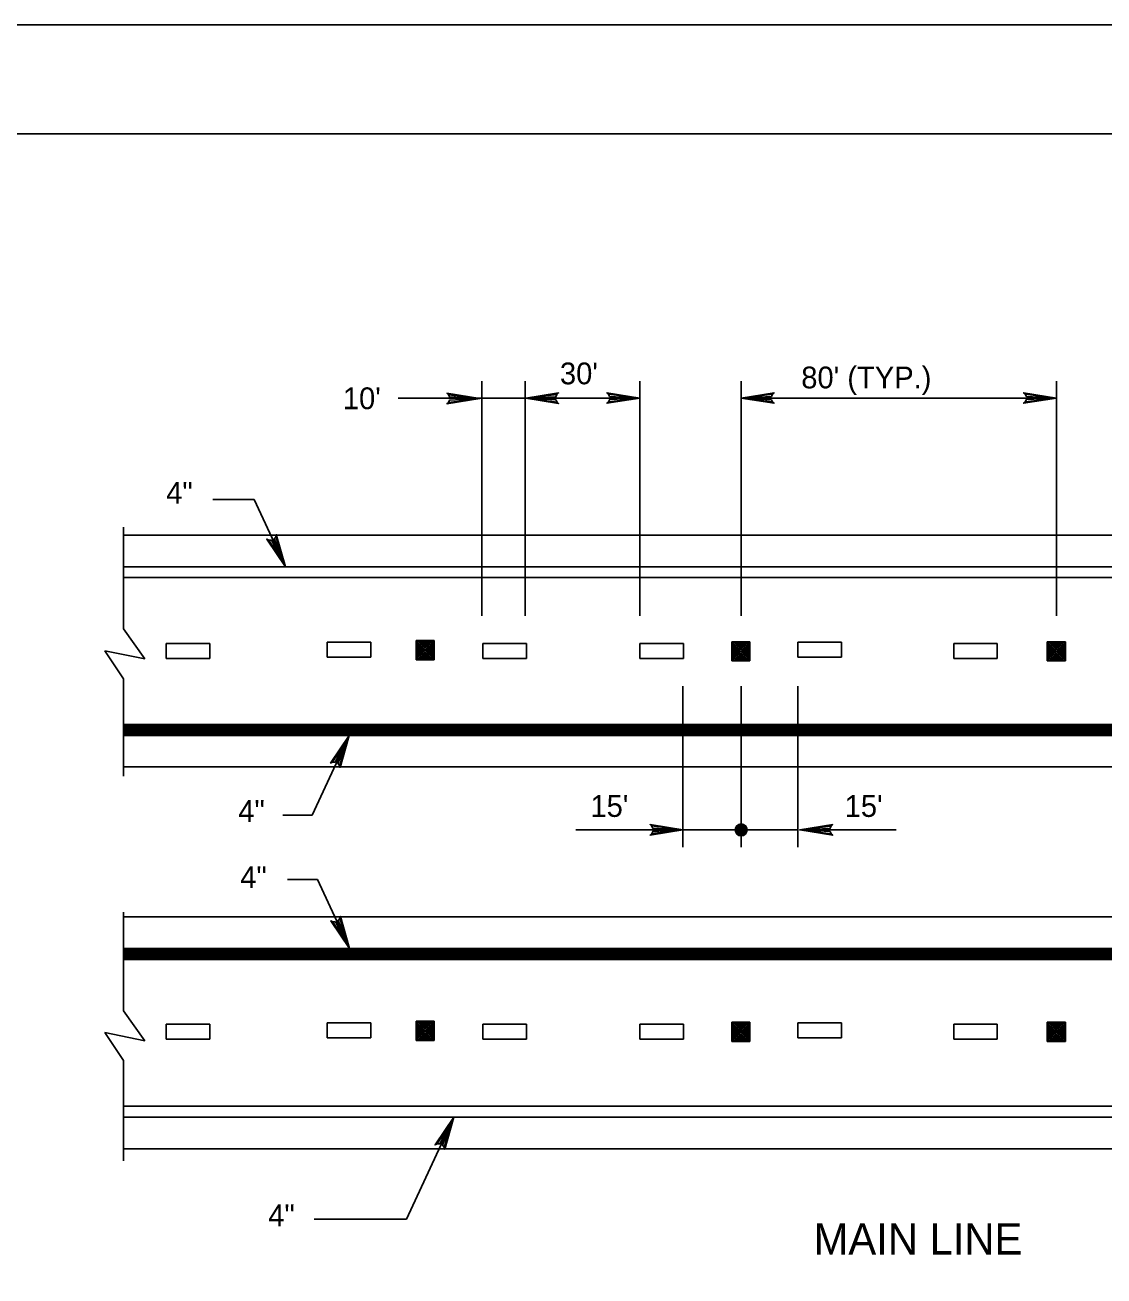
# Model space of a CAD drawing. Extents: x 639362 to 641108, y 298458 to 299646.
# Drawn here: x 639830.9 to 639979.6, y 299473.3 to 299645.6 of the extents above; entities that cross this region are included whole.
import ezdxf

# ---------------------------------------------------------------- set-up
doc = ezdxf.new("R2010")
doc.units = 0
for name, color, linetype in [('1', 7, 'Continuous'), ('2', 7, 'Continuous'), ('PLT-BNDY', 7, 'Continuous')]:
    doc.layers.add(name, color=color, linetype=linetype)

msp = doc.modelspace()

# ---------------------------------------------------------------- linework, layer by layer
at = {"layer": '1'}
msp.add_line((639402.31, 299630.63), (640188.31, 299630.63), dxfattribs=at)
at = {"layer": '2'}
for p, q in [((639893.88, 299564.2), (639893.88, 299596.53)), ((639899.82, 299564.2), (639899.82, 299596.53)), ((639915.64, 299564.2), (639915.64, 299596.53)), ((639929.6, 299564.2), (639929.6, 299596.53)), ((639973.04, 299564.2), (639973.04, 299596.53)), ((639882.34, 299594.23), (639899.82, 299594.23)), ((639899.82, 299594.23), (639915.64, 299594.23)), ((639973.04, 299594.23), (639929.6, 299594.23)), ((639856.81, 299580.26), (639862.49, 299580.26)), ((639862.49, 299580.26), (639866.8, 299570.98)), ((639844.48, 299576.44), (639844.48, 299562.41)), ((639844.48, 299575.33), (640078.99, 299575.33)), ((639844.48, 299570.98), (640078.99, 299570.98)), ((639844.48, 299569.48), (640078.99, 299569.48)), ((639847.43, 299558.27), (639844.48, 299562.41)), ((639850.37, 299558.33), (639850.37, 299560.39)), ((639850.37, 299560.39), (639856.39, 299560.39)), ((639856.39, 299560.39), (639856.39, 299558.33)), ((639872.56, 299558.51), (639872.56, 299560.58)), ((639872.56, 299560.58), (639878.58, 299560.58)), ((639878.58, 299560.58), (639878.58, 299558.51)), ((639887.32, 299560.81), (639884.82, 299560.81)), ((639884.82, 299560.81), (639884.82, 299558.16)), ((639887.13, 299560.68), (639885.01, 299560.68)), ((639885.01, 299560.68), (639885.01, 299558.29)), ((639886.96, 299560.51), (639885.18, 299560.51)), ((639885.18, 299560.51), (639885.18, 299558.47)), ((639886.78, 299560.33), (639885.36, 299560.33)), ((639885.36, 299560.33), (639885.36, 299558.64)), ((639886.6, 299560.15), (639885.54, 299560.15)), ((639885.54, 299560.15), (639885.54, 299558.82)), ((639886.6, 299558.82), (639886.6, 299560.15)), ((639886.78, 299558.64), (639886.78, 299560.33)), ((639886.96, 299558.47), (639886.96, 299560.51)), ((639887.13, 299558.29), (639887.13, 299560.68)), ((639887.32, 299558.16), (639887.32, 299560.81)), ((639894.01, 299558.33), (639894.01, 299560.39)), ((639894.01, 299560.39), (639900.02, 299560.39)), ((639900.02, 299560.39), (639900.02, 299558.33)), ((639915.64, 299558.33), (639915.64, 299560.39)), ((639915.64, 299560.39), (639921.65, 299560.39)), ((639921.65, 299560.39), (639921.65, 299558.33)), ((639928.31, 299560.65), (639930.81, 299560.65)), ((639928.31, 299558), (639928.31, 299560.65)), ((639928.5, 299560.52), (639930.63, 299560.52)), ((639928.5, 299558.12), (639928.5, 299560.52)), ((639928.68, 299560.34), (639930.45, 299560.34)), ((639928.68, 299558.3), (639928.68, 299560.34)), ((639928.85, 299560.16), (639930.27, 299560.16)), ((639928.85, 299558.48), (639928.85, 299560.16)), ((639930.27, 299560.16), (639930.27, 299558.48)), ((639930.45, 299560.34), (639930.45, 299558.3)), ((639930.63, 299560.52), (639930.63, 299558.12)), ((639930.81, 299560.65), (639930.81, 299558)), ((639937.42, 299558.51), (639937.42, 299560.58)), ((639937.42, 299560.58), (639943.44, 299560.58)), ((639943.44, 299560.58), (639943.44, 299558.51)), ((639958.88, 299558.33), (639958.88, 299560.39)), ((639958.88, 299560.39), (639964.89, 299560.39)), ((639964.89, 299560.39), (639964.89, 299558.33)), ((639974.28, 299560.65), (639971.78, 299560.65)), ((639971.78, 299560.65), (639971.78, 299558)), ((639974.09, 299560.52), (639971.96, 299560.52)), ((639971.96, 299560.52), (639971.96, 299558.12)), ((639973.92, 299560.34), (639972.14, 299560.34)), ((639972.14, 299560.34), (639972.14, 299558.3)), ((639973.74, 299560.16), (639972.32, 299560.16)), ((639972.32, 299560.16), (639972.32, 299558.48)), ((639973.74, 299558.48), (639973.74, 299560.16)), ((639973.92, 299558.3), (639973.92, 299560.34)), ((639974.09, 299558.12), (639974.09, 299560.52)), ((639974.28, 299558), (639974.28, 299560.65)), ((639844.48, 299555.54), (639841.91, 299559.41)), ((639841.91, 299559.41), (639847.43, 299558.27)), ((639878.58, 299558.51), (639872.56, 299558.51)), ((639885.18, 299558.47), (639886.96, 299558.47)), ((639885.36, 299558.64), (639886.78, 299558.64)), ((639885.54, 299558.82), (639886.6, 299558.82)), ((639885.71, 299559.97), (639885.71, 299559)), ((639886.43, 299559.97), (639885.71, 299559.97)), ((639885.71, 299559), (639886.43, 299559)), ((639886.25, 299559.79), (639885.89, 299559.79)), ((639885.89, 299559.79), (639885.89, 299559.17)), ((639885.89, 299559.17), (639886.25, 299559.17)), ((639886.07, 299559.62), (639886.07, 299559.35)), ((639886.25, 299559.17), (639886.25, 299559.79)), ((639886.43, 299559), (639886.43, 299559.97)), ((639930.27, 299558.48), (639928.85, 299558.48)), ((639929.03, 299559.99), (639930.1, 299559.99)), ((639929.03, 299558.66), (639929.03, 299559.99)), ((639930.1, 299558.66), (639929.03, 299558.66)), ((639929.21, 299558.83), (639929.21, 299559.81)), ((639929.21, 299559.81), (639929.92, 299559.81)), ((639929.92, 299558.83), (639929.21, 299558.83)), ((639929.39, 299559.63), (639929.74, 299559.63)), ((639929.39, 299559.01), (639929.39, 299559.63)), ((639929.74, 299559.01), (639929.39, 299559.01)), ((639929.56, 299559.45), (639929.56, 299559.19)), ((639929.74, 299559.63), (639929.74, 299559.01)), ((639929.92, 299559.81), (639929.92, 299558.83)), ((639930.1, 299559.99), (639930.1, 299558.66)), ((639943.44, 299558.51), (639937.42, 299558.51)), ((639972.32, 299558.48), (639973.74, 299558.48)), ((639973.56, 299559.99), (639972.5, 299559.99)), ((639972.5, 299559.99), (639972.5, 299558.66)), ((639972.5, 299558.66), (639973.56, 299558.66)), ((639972.67, 299559.81), (639972.67, 299558.83)), ((639973.38, 299559.81), (639972.67, 299559.81)), ((639972.67, 299558.83), (639973.38, 299558.83)), ((639973.2, 299559.63), (639972.85, 299559.63)), ((639972.85, 299559.63), (639972.85, 299559.01)), ((639972.85, 299559.01), (639973.2, 299559.01)), ((639973.03, 299559.45), (639973.03, 299559.19)), ((639973.2, 299559.01), (639973.2, 299559.63)), ((639973.38, 299558.83), (639973.38, 299559.81)), ((639973.56, 299558.66), (639973.56, 299559.99)), ((639856.39, 299558.33), (639850.37, 299558.33)), ((639884.82, 299558.16), (639887.32, 299558.16)), ((639885.01, 299558.29), (639887.13, 299558.29)), ((639900.02, 299558.33), (639894.01, 299558.33)), ((639921.65, 299558.33), (639915.64, 299558.33)), ((639930.81, 299558), (639928.31, 299558)), ((639930.63, 299558.12), (639928.5, 299558.12)), ((639930.45, 299558.3), (639928.68, 299558.3)), ((639964.89, 299558.33), (639958.88, 299558.33)), ((639971.78, 299558), (639974.28, 299558)), ((639971.96, 299558.12), (639974.09, 299558.12)), ((639972.14, 299558.3), (639973.92, 299558.3)), ((639844.48, 299555.54), (639844.48, 299542.1)), ((639921.57, 299554.52), (639921.57, 299532.35)), ((639929.6, 299554.52), (639929.6, 299532.35)), ((639937.4, 299554.52), (639937.4, 299532.35)), ((639844.48, 299549.24), (640078.99, 299549.24)), ((639844.48, 299549.09), (640078.99, 299549.09)), ((639844.48, 299548.94), (640078.99, 299548.94)), ((639844.48, 299548.79), (640078.99, 299548.79)), ((639844.48, 299548.64), (640078.99, 299548.64)), ((639844.48, 299548.49), (640078.99, 299548.49)), ((639844.48, 299548.34), (640078.99, 299548.34)), ((639844.48, 299548.19), (640078.99, 299548.19)), ((639844.48, 299548.04), (640078.99, 299548.04)), ((639844.48, 299547.89), (640078.99, 299547.89)), ((639844.48, 299547.74), (640078.99, 299547.74)), ((639870.5, 299536.76), (639875.59, 299547.74)), ((639844.48, 299543.39), (640078.99, 299543.39)), ((639866.45, 299536.76), (639870.5, 299536.76)), ((639921.57, 299534.72), (639906.84, 299534.72)), ((639921.57, 299534.72), (639937.4, 299534.72)), ((639937.63, 299534.72), (639950.97, 299534.72)), ((639867.08, 299527.87), (639871.22, 299527.87)), ((639871.22, 299527.87), (639875.63, 299518.37)), ((639844.48, 299523.39), (639844.48, 299509.8)), ((639844.48, 299522.72), (640078.99, 299522.72)), ((639844.48, 299518.37), (640078.99, 299518.37)), ((639844.48, 299518.22), (640078.99, 299518.22)), ((639844.48, 299518.07), (640078.99, 299518.07)), ((639844.48, 299517.92), (640078.99, 299517.92)), ((639844.48, 299517.77), (640078.99, 299517.77)), ((639844.48, 299517.62), (640078.99, 299517.62)), ((639844.48, 299517.47), (640078.99, 299517.47)), ((639844.48, 299517.32), (640078.99, 299517.32)), ((639844.48, 299517.17), (640078.99, 299517.17)), ((639844.48, 299517.02), (640078.99, 299517.02)), ((639844.48, 299516.87), (640078.99, 299516.87)), ((639847.43, 299505.67), (639844.48, 299509.8)), ((639844.48, 299502.93), (639841.91, 299506.8)), ((639841.91, 299506.8), (639847.43, 299505.67)), ((639850.37, 299505.88), (639850.37, 299507.94)), ((639850.37, 299507.94), (639856.39, 299507.94)), ((639856.39, 299507.94), (639856.39, 299505.88)), ((639872.56, 299506.07), (639872.56, 299508.13)), ((639872.56, 299508.13), (639878.58, 299508.13)), ((639878.58, 299508.13), (639878.58, 299506.07)), ((639887.32, 299508.37), (639884.82, 299508.37)), ((639884.82, 299508.37), (639884.82, 299505.71)), ((639887.13, 299508.24), (639885.01, 299508.24)), ((639885.01, 299508.24), (639885.01, 299505.84)), ((639886.96, 299508.06), (639885.18, 299508.06)), ((639885.18, 299508.06), (639885.18, 299506.02)), ((639886.78, 299507.88), (639885.36, 299507.88)), ((639885.36, 299507.88), (639885.36, 299506.2)), ((639886.6, 299507.7), (639885.54, 299507.7)), ((639885.54, 299507.7), (639885.54, 299506.37)), ((639885.71, 299507.53), (639885.71, 299506.55)), ((639886.43, 299507.53), (639885.71, 299507.53)), ((639886.25, 299507.35), (639885.89, 299507.35)), ((639885.89, 299507.35), (639885.89, 299506.73)), ((639885.89, 299506.73), (639886.25, 299506.73)), ((639886.07, 299507.17), (639886.07, 299506.91)), ((639886.25, 299506.73), (639886.25, 299507.35)), ((639886.43, 299506.55), (639886.43, 299507.53)), ((639886.6, 299506.37), (639886.6, 299507.7)), ((639886.78, 299506.2), (639886.78, 299507.88)), ((639886.96, 299506.02), (639886.96, 299508.06)), ((639887.13, 299505.84), (639887.13, 299508.24)), ((639887.32, 299505.71), (639887.32, 299508.37)), ((639894.01, 299505.88), (639894.01, 299507.94)), ((639894.01, 299507.94), (639900.02, 299507.94)), ((639900.02, 299507.94), (639900.02, 299505.88)), ((639915.64, 299505.88), (639915.64, 299507.94)), ((639915.64, 299507.94), (639921.65, 299507.94)), ((639921.65, 299507.94), (639921.65, 299505.88)), ((639928.31, 299508.21), (639930.81, 299508.21)), ((639928.31, 299505.55), (639928.31, 299508.21)), ((639928.5, 299508.07), (639930.63, 299508.07)), ((639928.5, 299505.68), (639928.5, 299508.07)), ((639928.68, 299507.9), (639930.45, 299507.9)), ((639928.68, 299505.86), (639928.68, 299507.9)), ((639928.85, 299507.72), (639930.27, 299507.72)), ((639928.85, 299506.03), (639928.85, 299507.72)), ((639929.03, 299507.54), (639930.1, 299507.54)), ((639929.03, 299506.21), (639929.03, 299507.54)), ((639929.21, 299506.39), (639929.21, 299507.36)), ((639929.21, 299507.36), (639929.92, 299507.36)), ((639929.39, 299507.19), (639929.74, 299507.19)), ((639929.39, 299506.57), (639929.39, 299507.19)), ((639929.56, 299507.01), (639929.56, 299506.74)), ((639929.74, 299507.19), (639929.74, 299506.57)), ((639929.92, 299507.36), (639929.92, 299506.39)), ((639930.1, 299507.54), (639930.1, 299506.21)), ((639930.27, 299507.72), (639930.27, 299506.03)), ((639930.45, 299507.9), (639930.45, 299505.86)), ((639930.63, 299508.07), (639930.63, 299505.68)), ((639930.81, 299508.21), (639930.81, 299505.55)), ((639937.42, 299506.07), (639937.42, 299508.13)), ((639937.42, 299508.13), (639943.44, 299508.13)), ((639943.44, 299508.13), (639943.44, 299506.07)), ((639958.88, 299505.88), (639958.88, 299507.94)), ((639958.88, 299507.94), (639964.89, 299507.94)), ((639964.89, 299507.94), (639964.89, 299505.88)), ((639974.28, 299508.21), (639971.78, 299508.21)), ((639971.78, 299508.21), (639971.78, 299505.55)), ((639974.09, 299508.07), (639971.96, 299508.07)), ((639971.96, 299508.07), (639971.96, 299505.68)), ((639973.92, 299507.9), (639972.14, 299507.9)), ((639972.14, 299507.9), (639972.14, 299505.86)), ((639973.74, 299507.72), (639972.32, 299507.72)), ((639972.32, 299507.72), (639972.32, 299506.03)), ((639973.56, 299507.54), (639972.5, 299507.54)), ((639972.5, 299507.54), (639972.5, 299506.21)), ((639972.67, 299507.36), (639972.67, 299506.39)), ((639973.38, 299507.36), (639972.67, 299507.36)), ((639973.2, 299507.19), (639972.85, 299507.19)), ((639972.85, 299507.19), (639972.85, 299506.57)), ((639973.03, 299507.01), (639973.03, 299506.74)), ((639973.2, 299506.57), (639973.2, 299507.19)), ((639973.38, 299506.39), (639973.38, 299507.36)), ((639973.56, 299506.21), (639973.56, 299507.54)), ((639973.74, 299506.03), (639973.74, 299507.72)), ((639973.92, 299505.86), (639973.92, 299507.9)), ((639974.09, 299505.68), (639974.09, 299508.07)), ((639974.28, 299505.55), (639974.28, 299508.21)), ((639856.39, 299505.88), (639850.37, 299505.88)), ((639878.58, 299506.07), (639872.56, 299506.07)), ((639884.82, 299505.71), (639887.32, 299505.71)), ((639885.01, 299505.84), (639887.13, 299505.84)), ((639885.18, 299506.02), (639886.96, 299506.02)), ((639885.36, 299506.2), (639886.78, 299506.2)), ((639885.54, 299506.37), (639886.6, 299506.37)), ((639885.71, 299506.55), (639886.43, 299506.55)), ((639900.02, 299505.88), (639894.01, 299505.88)), ((639921.65, 299505.88), (639915.64, 299505.88)), ((639930.81, 299505.55), (639928.31, 299505.55)), ((639930.63, 299505.68), (639928.5, 299505.68)), ((639930.45, 299505.86), (639928.68, 299505.86)), ((639930.27, 299506.03), (639928.85, 299506.03)), ((639930.1, 299506.21), (639929.03, 299506.21)), ((639929.92, 299506.39), (639929.21, 299506.39)), ((639929.74, 299506.57), (639929.39, 299506.57)), ((639943.44, 299506.07), (639937.42, 299506.07)), ((639964.89, 299505.88), (639958.88, 299505.88)), ((639971.78, 299505.55), (639974.28, 299505.55)), ((639971.96, 299505.68), (639974.09, 299505.68)), ((639972.14, 299505.86), (639973.92, 299505.86)), ((639972.32, 299506.03), (639973.74, 299506.03)), ((639972.5, 299506.21), (639973.56, 299506.21)), ((639972.67, 299506.39), (639973.38, 299506.39)), ((639972.85, 299506.57), (639973.2, 299506.57)), ((639844.48, 299502.93), (639844.48, 299489.11)), ((639844.48, 299496.64), (640078.99, 299496.64)), ((639844.48, 299495.14), (640078.99, 299495.14)), ((639883.47, 299481.07), (639890, 299495.14)), ((639844.48, 299490.79), (640078.99, 299490.79)), ((639870.78, 299481.07), (639883.47, 299481.07))]:
    msp.add_line(p, q, dxfattribs=at)
for points in [[(639889.26, 299594.69), (639889.43, 299594.38), (639893.58, 299594.15), (639889.26, 299594.69), (639889.05, 299594.88), (639893.58, 299594.15), (639889.43, 299593.94), (639889.28, 299593.63), (639893.58, 299594.15), (639889.05, 299593.43), (639889.28, 299593.63)], [(639904.23, 299593.67), (639904.07, 299593.97), (639899.91, 299594.2), (639904.23, 299593.67), (639904.45, 299593.47), (639899.91, 299594.2), (639904.07, 299594.41), (639904.22, 299594.72), (639899.91, 299594.2), (639904.45, 299594.93), (639904.22, 299594.72)], [(639911.32, 299594.77), (639911.48, 299594.46), (639915.64, 299594.23), (639911.32, 299594.77), (639911.11, 299594.96), (639915.64, 299594.23), (639911.49, 299594.03), (639911.34, 299593.72), (639915.64, 299594.23), (639911.11, 299593.51), (639911.34, 299593.72)], [(639933.92, 299593.69), (639933.76, 299594), (639929.6, 299594.23), (639933.92, 299593.69), (639934.14, 299593.5), (639929.6, 299594.23), (639933.76, 299594.44), (639933.91, 299594.75), (639929.6, 299594.23), (639934.14, 299594.95), (639933.91, 299594.75)], [(639968.73, 299594.77), (639968.89, 299594.46), (639973.04, 299594.23), (639968.73, 299594.77), (639968.5, 299594.96), (639973.04, 299594.23), (639968.89, 299594.03), (639968.74, 299593.72), (639973.04, 299594.23), (639968.5, 299593.51), (639968.74, 299593.72)], [(639865.47, 299575.12), (639865.26, 299574.85), (639866.8, 299570.98), (639865.47, 299575.12), (639865.55, 299575.4), (639866.8, 299570.98), (639864.87, 299574.66), (639864.52, 299574.66), (639866.8, 299570.98), (639864.23, 299574.79), (639864.52, 299574.66)], [(639874.26, 299543.6), (639874.05, 299543.87), (639875.59, 299547.74), (639874.26, 299543.6), (639874.34, 299543.32), (639875.59, 299547.74), (639873.66, 299544.06), (639873.31, 299544.05), (639875.59, 299547.74), (639873.03, 299543.93), (639873.31, 299544.05)], [(639917.26, 299535.26), (639917.42, 299534.95), (639921.57, 299534.72), (639917.26, 299535.26), (639917.04, 299535.45), (639921.57, 299534.72), (639917.42, 299534.52), (639917.27, 299534.2), (639921.57, 299534.72), (639917.04, 299534), (639917.27, 299534.2)], [(639942, 299534.18), (639941.84, 299534.49), (639937.68, 299534.72), (639942, 299534.18), (639942.22, 299533.99), (639937.68, 299534.72), (639941.83, 299534.92), (639941.99, 299535.23), (639937.68, 299534.72), (639942.22, 299535.44), (639941.99, 299535.23)], [(639874.3, 299522.51), (639874.09, 299522.24), (639875.63, 299518.37), (639874.3, 299522.51), (639874.38, 299522.79), (639875.63, 299518.37), (639873.69, 299522.05), (639873.35, 299522.06), (639875.63, 299518.37), (639873.06, 299522.18), (639873.35, 299522.06)], [(639888.67, 299490.99), (639888.46, 299491.27), (639890, 299495.14), (639888.67, 299490.99), (639888.75, 299490.71), (639890, 299495.14), (639888.07, 299491.45), (639887.72, 299491.45), (639890, 299495.14), (639887.43, 299491.32), (639887.72, 299491.45)]]:
    msp.add_lwpolyline(points, dxfattribs=at)
for radius in [0.817, 0.759, 0.701, 0.643, 0.585, 0.527, 0.469, 0.411, 0.353, 0.295, 0.237, 0.179, 0.121, 0.0627]:
    msp.add_circle((639929.6, 299534.72), radius, dxfattribs=at)
at = {"layer": 'PLT-BNDY'}
msp.add_lwpolyline([(639362.31, 299645.63), (640203.31, 299645.63), (640203.31, 299051.63), (639362.31, 299051.63)], close=True, dxfattribs=at)

# ---------------------------------------------------------------- texts
at = {"layer": '2'}
for s, height, p in [("30'", 3, (639904.63, 299596.12)), ("80' (TYP.)", 3, (639937.88, 299595.56)), ("10'", 3, (639874.72, 299592.69)), ('4"', 3, (639850.38, 299579.67)), ("15'", 3, (639908.83, 299536.51)), ("15'", 3, (639943.86, 299536.51)), ('4"', 3, (639860.31, 299535.82)), ('4"', 3, (639860.58, 299526.72)), ('4"', 3, (639864.44, 299480.11)), ('MAIN LINE', 4.3, (639939.58, 299476.2))]:
    msp.add_text(s, height=height, dxfattribs=at).set_placement(p)

doc.saveas('drawing.dxf')
